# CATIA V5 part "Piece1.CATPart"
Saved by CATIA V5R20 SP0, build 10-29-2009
Part number: Piece1
Bounding box of the stored display mesh (mm): x -14 to 3.606, y -21.84 to 70.146, z -63.42 to 2.999
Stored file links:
  D:\Dropbox\IAO_2012\IAO_2012_815_gcordenod\gcordenod\Piece1.CATPart
  F:\TRAV\IAO\Exercice IAO\Catia\Assemblage_regulateur.CATProduct
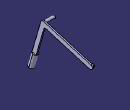
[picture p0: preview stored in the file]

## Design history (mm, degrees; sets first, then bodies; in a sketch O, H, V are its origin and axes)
External parameters (linked from other documents)
  External.AB = 70 mm
Set1
  Point1 "B": linked copy from another document
  Point2 "A": linked copy from another document
  Line1: linked copy from another document
  Point3 "A": linked copy from another document
Body1 (main body)
  Point4 "B": stored without definition
  Point5 "A": stored without definition
  Line2: stored without definition
  Line3: stored without definition
  Point6 "B": stored without definition
  Point7 "A": stored without definition
  Point8 "A": stored without definition
  Line4: stored without definition
  Line5: stored without definition
  Point9 "B": stored without definition
  Point10 "A": stored without definition
  Sketch1 on yz-plane, origin (0, 0, 0), H (0, 1, 0), V (0, 0, 1)
    line L1 (66.2998, -22.657) -> (3.9987, -4.3053)
    arc A1 centre (3.4188, -6.274) radius 2.0523 from (3.9987, -4.3053) to (1.4502, -5.6941) ccw
    line L2 (1.4502, -5.6941) -> (-15.5035, -63.249)
    line L3 (-15.5035, -63.249) -> (-21.259, -61.5537)
    arc A2 centre (0, 0) radius 3 from (-2.8777, 0.8477) to (0.8477, 2.8777) cw
    arc A3 centre (67.1475, -19.7793) radius 3 from (67.9951, -16.9015) to (66.2998, -22.657) cw
    point P11 (67.1475, -19.7793)
    line L4 (67.9951, -16.9015) -> (0.8477, 2.8777)
    line L5 (-2.8777, 0.8477) -> (-21.259, -61.5537)
    reference projected line E1 (0, 0) -> (47.9625, -14.128) from Line4
    reference projected line E2 (0, 0) -> (47.9625, -14.128) from Line4
    reference projected line E3 (0, 0) -> (47.9625, -14.128) from Line5
    reference projected point E4 (0, 0) from Point10
    reference projected point E5 (0, 0) from Point2
    reference projected line E6 (0, 0) -> (67.1475, -19.7793) from Line1
    distance L1 L4 = 6
    distance L2 L5 = 6
    length L2 = 60
    distance P11 E5 = 70 {= External.AB}
    tangency: A1 L1, L2 A1, A3 L1, L5 A2, L4 A2
    perpendicularity: L3 L2, L5 L3, L1 L2
    parallelism: L4 E1, E2 L1
    symmetry: L1 L4 E3
    concentricity: A2 E4
    coincidence: P11 E6
  Pad1: profile Sketch1, direction (1, 0, 0), length 2
  Point11 "A": stored without definition
  DatumCurve1
  Point12 "B": stored without definition
  Sketch2 on start face of Pad1, origin (0, 0, 0), H (0, -1, 0), V (0, 0, 1)
    circle A1 centre (0, 0) radius 2
    point P1 (0, 0)
    reference projected point E1 (0, 0) from Point11
    reference projected circle E2 centre (0, 0) radius 2 from edge of DatumCurve1
    circle A2 centre (-67.1475, -19.7793) radius 1.9641
    point P2 (-67.1475, -19.7793)
    reference projected point E3 (0, 0) from Point2
    reference projected line E4 (0, 0) -> (-67.1475, -19.7793) from Line1
    radius A2 = 1.9641
    distance E3 P2 = 70 {= External.AB}
    coincidence: E1 P1, A1 E2, P2 E4
  Pad2: profile Sketch2, direction (-1, 0, 0), length 2
  Sketch3 on face of Pad1 from Sketch1.L3, origin (0, -18.3812, -62.4014), H (1, 0, 0), V (0, -0.9592, 0.2826)
    circle A1 centre (0, 0) radius 3.6056
    point P1 (0, 0)
    reference intersected line E1 (0, -3) -> (0, 3) from start face of Pad1
    reference projected point E2 (2, 3) from vertex [face of Pad1 from Sketch1.L3 | end face of Pad1 | face of Pad1 from Sketch1.L5]
    reference projected point E3 (2, -3) from vertex [face of Pad1 from Sketch1.L2 | end face of Pad1 | face of Pad1 from Sketch1.L3]
    coincidence: P1 E1, E2 A1, E3 A1
  Pad3: profile Sketch3, direction (0, 0.2826, 0.9592), length 20
  Point13 "A": stored without definition
  Sketch4 on end face of Pad2, origin (-2, 0, 0), H (0, -1, 0), V (0, 0, 1)
    circle A1 centre (0, 0) radius 2
    point P1 (0, 0)
    reference projected point E1 (0, 0) from Point13
    radius A1 = 2
    coincidence: E1 P1
  Pad4: profile Sketch4, direction (-1, 0, 0), length 12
